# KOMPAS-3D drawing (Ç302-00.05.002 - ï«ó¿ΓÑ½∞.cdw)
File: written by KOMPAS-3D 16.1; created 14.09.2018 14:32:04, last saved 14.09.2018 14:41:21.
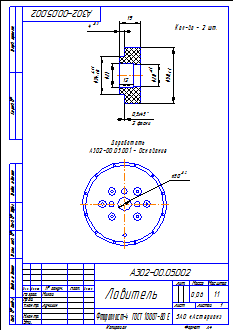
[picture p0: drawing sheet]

Sheet 1: A4, portrait

Title block, sheet 1: name: Ловитель; designation: А302-00.05.002; material: Фторопласт-4  ГОСТ 10007-80 Е; mass: 0,06; scale: 1:1; sheets: 1; organisation: ЗАО «Астерион»; sheet format: A4; stored path: Z:\Мембранные насосы\Мембранный электропривод\А302-00.00.000 - ASTRA-302 (МЭ200)\3Д\Доработка\А302-00.05.002 - Ловитель.cdw; drawn by: Милов; technical control: Лучихин

Views: Вид 1, Местный разрез 1, Спереди, Проекционный вид 2, Вид 3, Вид:1, Вид:2
Referenced files in Z:\Мембранные насосы\Мембранный электропривод\А302-00.00.000 - ASTRA-302 (МЭ200)\3Д\Доработка\: А302-00.05.002 - Ловитель-1.m3d
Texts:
  Кол-во - 2 шт.
  Доработать
  А302-00.05.001 - Основание
Dimensions and other numbers on the sheet: 20; 21; 34; 50; 4; 19; 0,5; 2 фаски; 12; 1:1; 1; 0,06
